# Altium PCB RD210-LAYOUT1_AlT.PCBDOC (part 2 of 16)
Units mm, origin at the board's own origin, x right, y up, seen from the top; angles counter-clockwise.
Board outline 330 x 300 mm, 6 copper layers (TOP, Mid-Layer 1, Mid-Layer 2, Mid-Layer 3, Mid-Layer 4, BOTTOM), stack 1.422 mm thick; 981 components, 463 nets, 2326 pads, 12534 vias.
Unrouted connection lines stored in the file: 6.
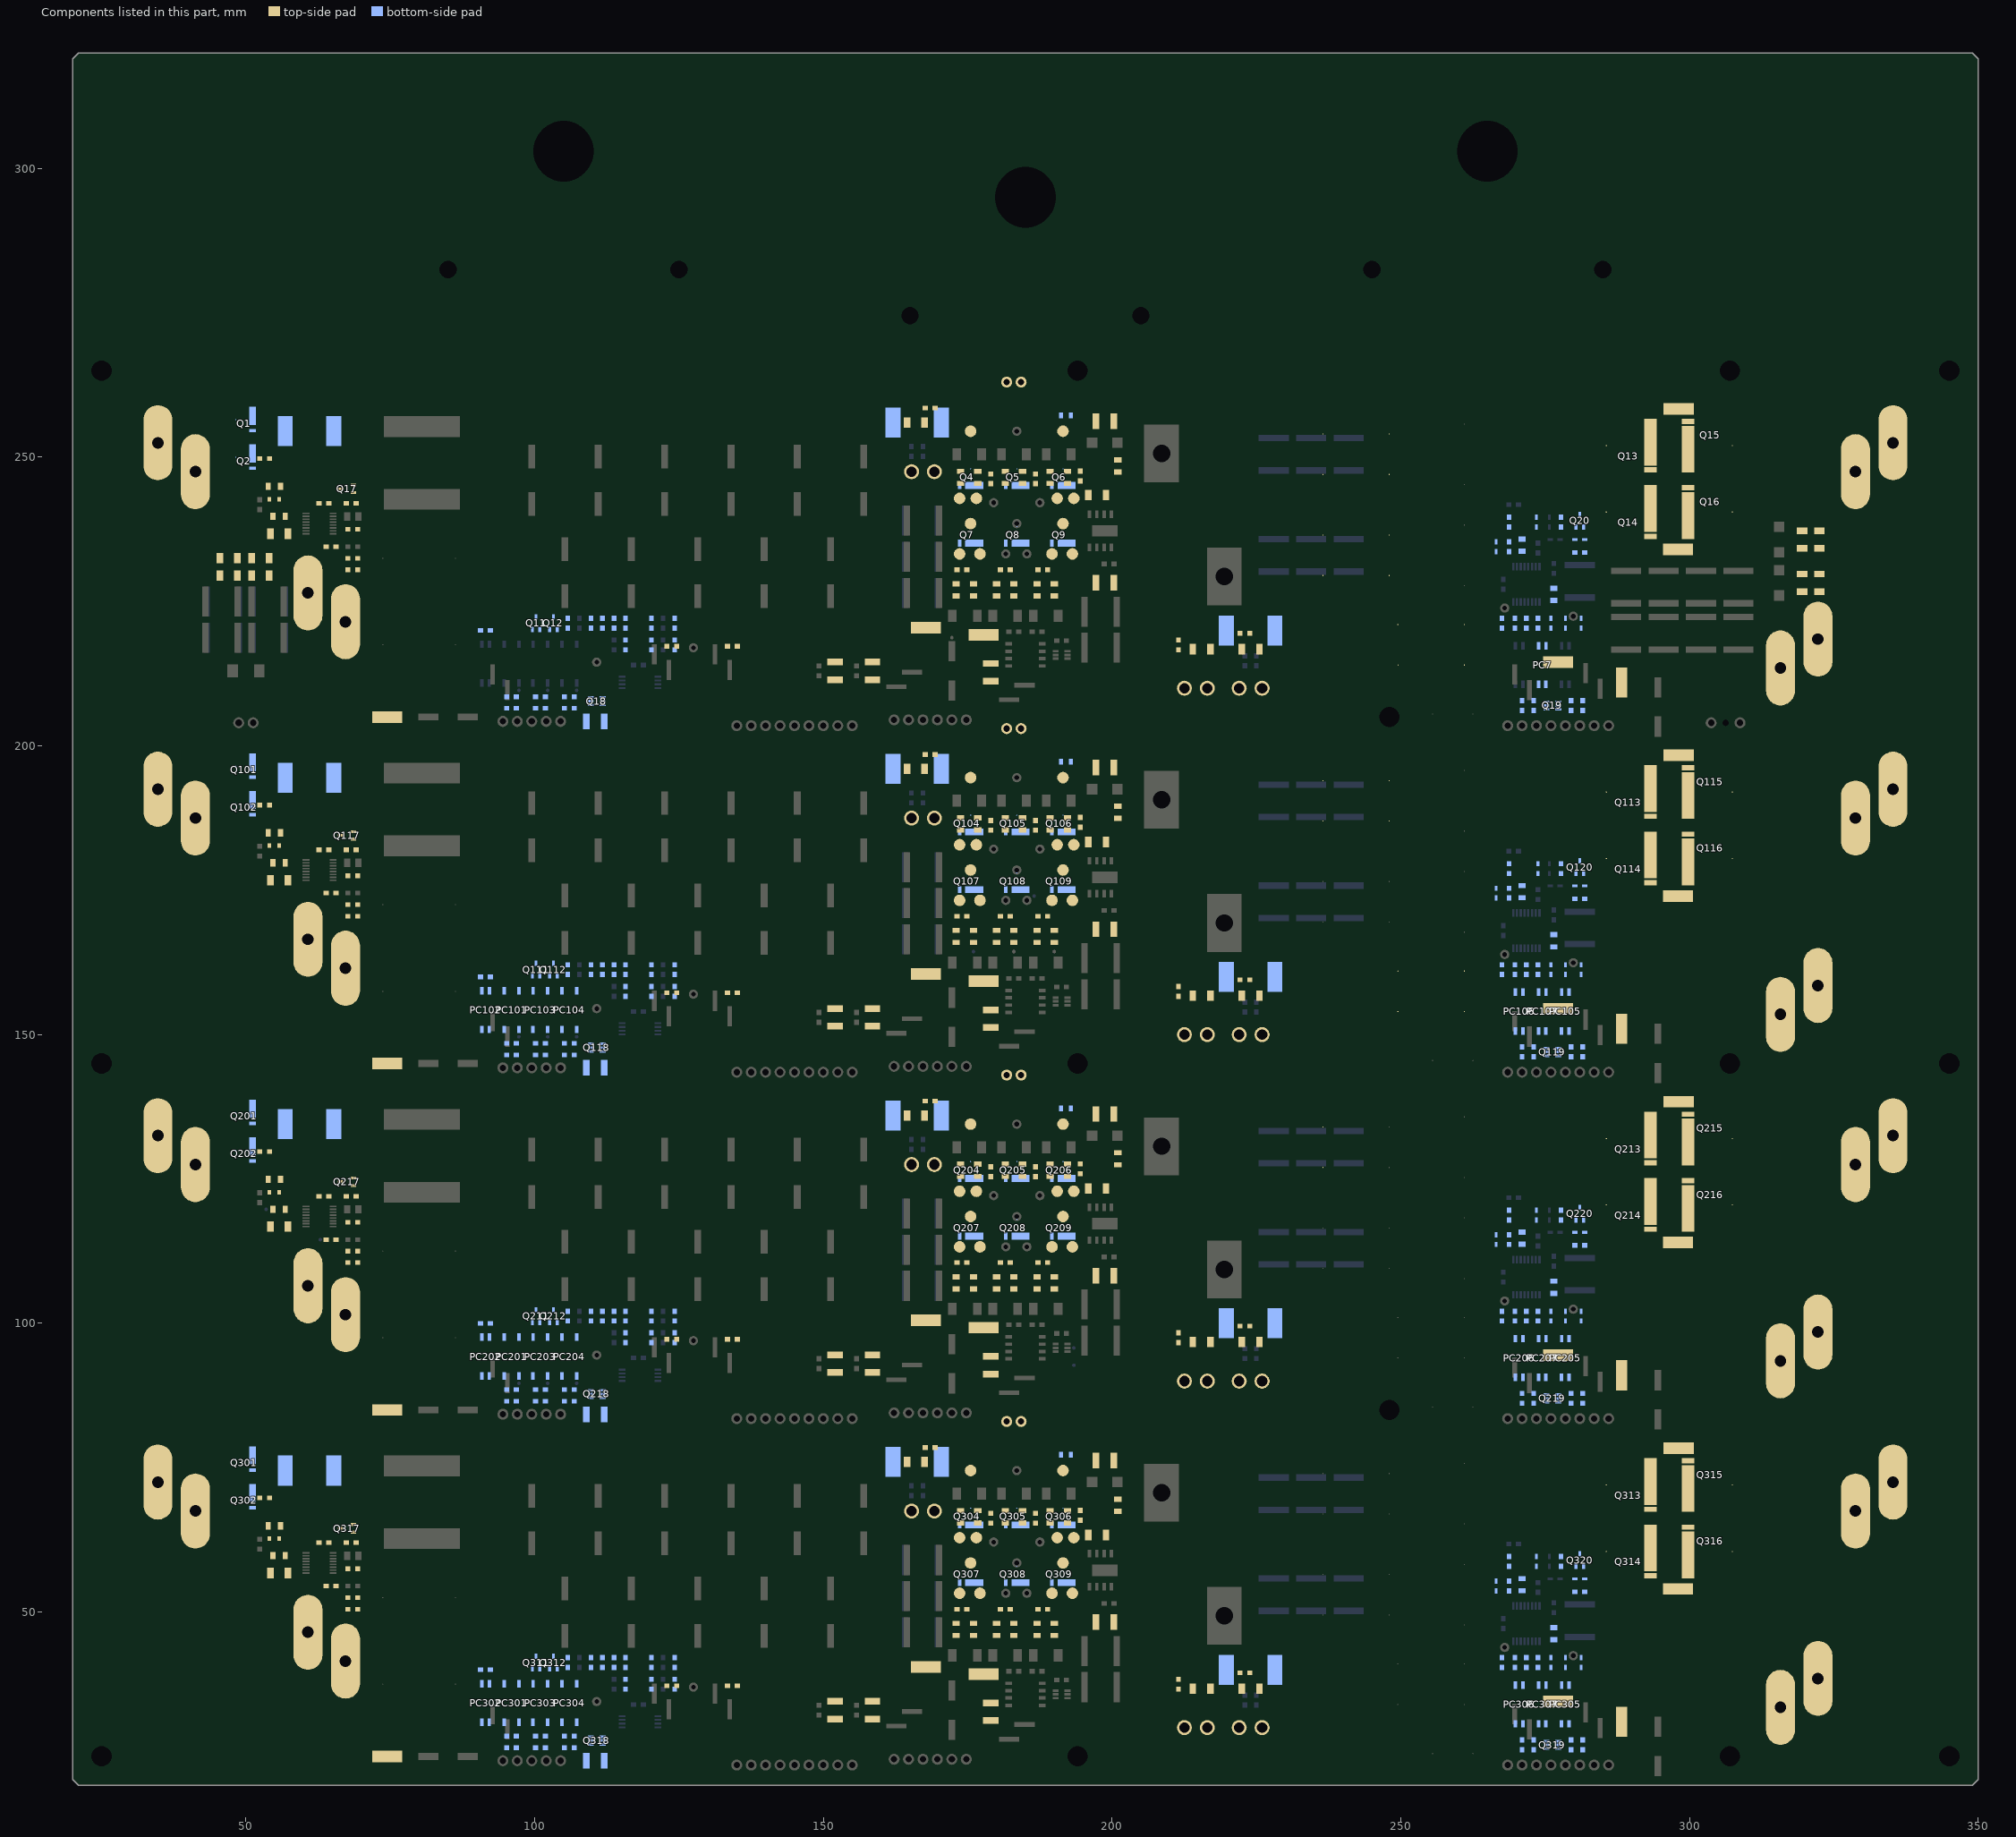
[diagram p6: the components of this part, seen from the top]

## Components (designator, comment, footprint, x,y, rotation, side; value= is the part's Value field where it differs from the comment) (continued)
PC7 "S4P_PC-2.6x4.55?2.1-PX1.27-PY7+3" S4P_PC-2.6x4.55?2.1-PX1.27-PY7+3 274.5,214 r180 bottom
PC101 "S4P_PC-3.7?4.55?2.1-PX2.54-PY7+3" S4P_PC-3.7?4.55?2.1-PX2.54-PY7+3 96,154.25 r0 bottom
PC102 "S4P_PC-2.6x4.55?2.1-PX1.27-PY7+4" S4P_PC-2.6x4.55?2.1-PX1.27-PY7+4 91.5,154.25 r180 bottom
PC103 "S4P_PC-3.7?4.55?2.1-PX2.54-PY7+4" S4P_PC-3.7?4.55?2.1-PX2.54-PY7+4 101,154.25 r0 bottom
PC104 "S4P_PC-3.7?4.55?2.1-PX2.54-PY7+5" S4P_PC-3.7?4.55?2.1-PX2.54-PY7+5 106,154.25 r0 bottom
PC105 "S4P_PC-2.6x4.55?2.1-PX1.27-PY7+5" S4P_PC-2.6x4.55?2.1-PX1.27-PY7+5 278.5,154 r0 bottom
PC106 "S4P_PC-2.6x4.55?2.1-PX1.27-PY7+6" S4P_PC-2.6x4.55?2.1-PX1.27-PY7+6 270.5,154 r0 bottom
PC107 "S4P_PC-2.6x4.55?2.1-PX1.27-PY7+7" S4P_PC-2.6x4.55?2.1-PX1.27-PY7+7 274.5,154 r180 bottom
PC201 "S4P_PC-3.7?4.55?2.1-PX2.54-PY7+6" S4P_PC-3.7?4.55?2.1-PX2.54-PY7+6 96,94.25 r0 bottom
PC202 "S4P_PC-2.6x4.55?2.1-PX1.27-PY7+8" S4P_PC-2.6x4.55?2.1-PX1.27-PY7+8 91.5,94.25 r180 bottom
PC203 "S4P_PC-3.7?4.55?2.1-PX2.54-PY7+7" S4P_PC-3.7?4.55?2.1-PX2.54-PY7+7 101,94.25 r0 bottom
PC204 "S4P_PC-3.7?4.55?2.1-PX2.54-PY7+8" S4P_PC-3.7?4.55?2.1-PX2.54-PY7+8 106,94.25 r0 bottom
PC205 "S4P_PC-2.6x4.55?2.1-PX1.27-PY7+9" S4P_PC-2.6x4.55?2.1-PX1.27-PY7+9 278.5,94 r0 bottom
PC206 "S4P_PC-2.6x4.55?2.1-PX1.27-PY7+10" S4P_PC-2.6x4.55?2.1-PX1.27-PY7+10 270.5,94 r0 bottom
PC207 "S4P_PC-2.6x4.55?2.1-PX1.27-PY7+11" S4P_PC-2.6x4.55?2.1-PX1.27-PY7+11 274.5,94 r180 bottom
PC301 "S4P_PC-3.7?4.55?2.1-PX2.54-PY7+9" S4P_PC-3.7?4.55?2.1-PX2.54-PY7+9 96,34.25 r0 bottom
PC302 "S4P_PC-2.6x4.55?2.1-PX1.27-PY7+12" S4P_PC-2.6x4.55?2.1-PX1.27-PY7+12 91.5,34.25 r180 bottom
PC303 "S4P_PC-3.7?4.55?2.1-PX2.54-PY7+10" S4P_PC-3.7?4.55?2.1-PX2.54-PY7+10 101,34.25 r0 bottom
PC304 "S4P_PC-3.7?4.55?2.1-PX2.54-PY7+11" S4P_PC-3.7?4.55?2.1-PX2.54-PY7+11 106,34.25 r0 bottom
PC305 "S4P_PC-2.6x4.55?2.1-PX1.27-PY7+13" S4P_PC-2.6x4.55?2.1-PX1.27-PY7+13 278.5,34 r0 bottom
PC306 "S4P_PC-2.6x4.55?2.1-PX1.27-PY7+14" S4P_PC-2.6x4.55?2.1-PX1.27-PY7+14 270.5,34 r0 bottom
PC307 "S4P_PC-2.6x4.55?2.1-PX1.27-PY7+15" S4P_PC-2.6x4.55?2.1-PX1.27-PY7+15 274.5,34 r180 bottom
Q1 "S3P_FET-5x5x1-PX1.27-PY6+22" S3P_FET-5x5x1-PX1.27-PY6+22 48.25,256.5 r90 bottom
Q2 "S3P_FET-5x5x1-PX1.27-PY6+23" S3P_FET-5x5x1-PX1.27-PY6+23 48.25,250 r90 bottom
Q4 "S3P_FET-5x5x1-PX1.27-PY6" S3P_FET-5x5x1-PX1.27-PY6 175.5,248 r0 bottom
Q5 "S3P_FET-5x5x1-PX1.27-PY6+2" S3P_FET-5x5x1-PX1.27-PY6+2 183.5,248 r0 bottom
Q6 "S3P_FET-5x5x1-PX1.27-PY6+4" S3P_FET-5x5x1-PX1.27-PY6+4 191.5,248 r0 bottom
Q7 "S3P_FET-5x5x1-PX1.27-PY6+1" S3P_FET-5x5x1-PX1.27-PY6+1 175.5,238 r0 bottom
Q8 "S3P_FET-5x5x1-PX1.27-PY6+3" S3P_FET-5x5x1-PX1.27-PY6+3 183.5,238 r0 bottom
Q9 "S3P_FET-5x5x1-PX1.27-PY6+5" S3P_FET-5x5x1-PX1.27-PY6+5 191.5,238 r0 bottom
Q11 "S3P_Q-2x1.7x0.75-PX0.65-2.1" S3P_Q-2x1.7x0.75-PX0.65-2.1 100.25,221.25 r0 bottom
Q12 "S3P_Q-2x1.7x0.75-PX0.65-2.1+1" S3P_Q-2x1.7x0.75-PX0.65-2.1+1 103.25,221.25 r0 bottom
Q13 "S3P_Q-9.9x8.5-2.3-PX1.2-PY11.8" S3P_Q-9.9x8.5-2.3-PX1.2-PY11.8 287,252 r90 top
Q14 "S3P_Q-9.9x8.5-2.3-PX1.2-PY11.8+1" S3P_Q-9.9x8.5-2.3-PX1.2-PY11.8+1 287,240.5 r90 top
Q15 "S3P_Q-9.9x8.5-2.3-PX1.2-PY11.8+2" S3P_Q-9.9x8.5-2.3-PX1.2-PY11.8+2 306,252 r270 top
Q16 "S3P_Q-9.9x8.5-2.3-PX1.2-PY11.8+3" S3P_Q-9.9x8.5-2.3-PX1.2-PY11.8+3 306,240.5 r270 top
Q17 "S3P_Q-2x1.7x0.75-PX0.65-2.1+8" S3P_Q-2x1.7x0.75-PX0.65-2.1+8 67.5,244.5 r90 top
Q18 "S6P_U-2x1.25x0.95-PX0.65-PY2.1" S6P_U-2x1.25x0.95-PX0.65-PY2.1 110.75,207.75 r270 bottom
Q19 "S6P_U-2x1.25x0.95-PX0.65-PY2.1+1" S6P_U-2x1.25x0.95-PX0.65-PY2.1+1 276.25,207 r90 bottom
Q20 "S3P_Q-2.0x1.25x0.9-PX0.65-PY2.1" S3P_Q-2.0x1.25x0.9-PX0.65-PY2.1 281,239 r0 bottom
Q101 "S3P_FET-5x5x1-PX1.27-PY6+24" S3P_FET-5x5x1-PX1.27-PY6+24 48.25,196.5 r90 bottom
Q102 "S3P_FET-5x5x1-PX1.27-PY6+25" S3P_FET-5x5x1-PX1.27-PY6+25 48.25,190 r90 bottom
Q104 "S3P_FET-5x5x1-PX1.27-PY6+26" S3P_FET-5x5x1-PX1.27-PY6+26 175.5,188 r0 bottom
Q105 "S3P_FET-5x5x1-PX1.27-PY6+27" S3P_FET-5x5x1-PX1.27-PY6+27 183.5,188 r0 bottom
Q106 "S3P_FET-5x5x1-PX1.27-PY6+28" S3P_FET-5x5x1-PX1.27-PY6+28 191.5,188 r0 bottom
Q107 "S3P_FET-5x5x1-PX1.27-PY6+29" S3P_FET-5x5x1-PX1.27-PY6+29 175.5,178 r0 bottom
Q108 "S3P_FET-5x5x1-PX1.27-PY6+30" S3P_FET-5x5x1-PX1.27-PY6+30 183.5,178 r0 bottom
Q109 "S3P_FET-5x5x1-PX1.27-PY6+31" S3P_FET-5x5x1-PX1.27-PY6+31 191.5,178 r0 bottom
Q111 "S3P_Q-2x1.7x0.75-PX0.65-2.1+2" S3P_Q-2x1.7x0.75-PX0.65-2.1+2 100.25,161.25 r0 bottom
Q112 "S3P_Q-2x1.7x0.75-PX0.65-2.1+3" S3P_Q-2x1.7x0.75-PX0.65-2.1+3 103.25,161.25 r0 bottom
Q113 "S3P_Q-9.9x8.5-2.3-PX1.2-PY11.8+5" S3P_Q-9.9x8.5-2.3-PX1.2-PY11.8+5 287,192 r90 top
Q114 "S3P_Q-9.9x8.5-2.3-PX1.2-PY11.8+4" S3P_Q-9.9x8.5-2.3-PX1.2-PY11.8+4 287,180.5 r90 top
Q115 "S3P_Q-9.9x8.5-2.3-PX1.2-PY11.8+7" S3P_Q-9.9x8.5-2.3-PX1.2-PY11.8+7 306,192 r270 top
Q116 "S3P_Q-9.9x8.5-2.3-PX1.2-PY11.8+6" S3P_Q-9.9x8.5-2.3-PX1.2-PY11.8+6 306,180.5 r270 top
Q117 "S3P_Q-2x1.7x0.75-PX0.65-2.1+9" S3P_Q-2x1.7x0.75-PX0.65-2.1+9 67.5,184.5 r90 top
Q118 "S6P_U-2x1.25x0.95-PX0.65-PY2.1+2" S6P_U-2x1.25x0.95-PX0.65-PY2.1+2 110.75,147.75 r270 bottom
Q119 "S6P_U-2x1.25x0.95-PX0.65-PY2.1+3" S6P_U-2x1.25x0.95-PX0.65-PY2.1+3 276.25,147 r90 bottom
Q120 "S3P_Q-2.0x1.25x0.9-PX0.65-PY2.1+1" S3P_Q-2.0x1.25x0.9-PX0.65-PY2.1+1 281,179 r0 bottom
Q201 "S3P_FET-5x5x1-PX1.27-PY6+6" S3P_FET-5x5x1-PX1.27-PY6+6 48.25,136.5 r90 bottom
Q202 "S3P_FET-5x5x1-PX1.27-PY6+7" S3P_FET-5x5x1-PX1.27-PY6+7 48.25,130 r90 bottom
Q204 "S3P_FET-5x5x1-PX1.27-PY6+8" S3P_FET-5x5x1-PX1.27-PY6+8 175.5,128 r0 bottom
Q205 "S3P_FET-5x5x1-PX1.27-PY6+9" S3P_FET-5x5x1-PX1.27-PY6+9 183.5,128 r0 bottom
Q206 "S3P_FET-5x5x1-PX1.27-PY6+10" S3P_FET-5x5x1-PX1.27-PY6+10 191.5,128 r0 bottom
Q207 "S3P_FET-5x5x1-PX1.27-PY6+11" S3P_FET-5x5x1-PX1.27-PY6+11 175.5,118 r0 bottom
Q208 "S3P_FET-5x5x1-PX1.27-PY6+12" S3P_FET-5x5x1-PX1.27-PY6+12 183.5,118 r0 bottom
Q209 "S3P_FET-5x5x1-PX1.27-PY6+13" S3P_FET-5x5x1-PX1.27-PY6+13 191.5,118 r0 bottom
Q211 "S3P_Q-2x1.7x0.75-PX0.65-2.1+4" S3P_Q-2x1.7x0.75-PX0.65-2.1+4 100.25,101.25 r0 bottom
Q212 "S3P_Q-2x1.7x0.75-PX0.65-2.1+5" S3P_Q-2x1.7x0.75-PX0.65-2.1+5 103.25,101.25 r0 bottom
Q213 "S3P_Q-9.9x8.5-2.3-PX1.2-PY11.8+9" S3P_Q-9.9x8.5-2.3-PX1.2-PY11.8+9 287,132 r90 top
Q214 "S3P_Q-9.9x8.5-2.3-PX1.2-PY11.8+8" S3P_Q-9.9x8.5-2.3-PX1.2-PY11.8+8 287,120.5 r90 top
Q215 "S3P_Q-9.9x8.5-2.3-PX1.2-PY11.8+11" S3P_Q-9.9x8.5-2.3-PX1.2-PY11.8+11 306,132 r270 top
Q216 "S3P_Q-9.9x8.5-2.3-PX1.2-PY11.8+10" S3P_Q-9.9x8.5-2.3-PX1.2-PY11.8+10 306,120.5 r270 top
Q217 "S3P_Q-2x1.7x0.75-PX0.65-2.1+10" S3P_Q-2x1.7x0.75-PX0.65-2.1+10 67.5,124.5 r90 top
Q218 "S6P_U-2x1.25x0.95-PX0.65-PY2.1+4" S6P_U-2x1.25x0.95-PX0.65-PY2.1+4 110.75,87.75 r270 bottom
Q219 "S6P_U-2x1.25x0.95-PX0.65-PY2.1+5" S6P_U-2x1.25x0.95-PX0.65-PY2.1+5 276.25,87 r90 bottom
Q220 "S3P_Q-2.0x1.25x0.9-PX0.65-PY2.1+2" S3P_Q-2.0x1.25x0.9-PX0.65-PY2.1+2 281,119 r0 bottom
Q301 "S3P_FET-5x5x1-PX1.27-PY6+14" S3P_FET-5x5x1-PX1.27-PY6+14 48.25,76.5 r90 bottom
Q302 "S3P_FET-5x5x1-PX1.27-PY6+15" S3P_FET-5x5x1-PX1.27-PY6+15 48.25,70 r90 bottom
Q304 "S3P_FET-5x5x1-PX1.27-PY6+16" S3P_FET-5x5x1-PX1.27-PY6+16 175.5,68 r0 bottom
Q305 "S3P_FET-5x5x1-PX1.27-PY6+17" S3P_FET-5x5x1-PX1.27-PY6+17 183.5,68 r0 bottom
Q306 "S3P_FET-5x5x1-PX1.27-PY6+18" S3P_FET-5x5x1-PX1.27-PY6+18 191.5,68 r0 bottom
Q307 "S3P_FET-5x5x1-PX1.27-PY6+19" S3P_FET-5x5x1-PX1.27-PY6+19 175.5,58 r0 bottom
Q308 "S3P_FET-5x5x1-PX1.27-PY6+20" S3P_FET-5x5x1-PX1.27-PY6+20 183.5,58 r0 bottom
Q309 "S3P_FET-5x5x1-PX1.27-PY6+21" S3P_FET-5x5x1-PX1.27-PY6+21 191.5,58 r0 bottom
Q311 "S3P_Q-2x1.7x0.75-PX0.65-2.1+6" S3P_Q-2x1.7x0.75-PX0.65-2.1+6 100.25,41.25 r0 bottom
Q312 "S3P_Q-2x1.7x0.75-PX0.65-2.1+7" S3P_Q-2x1.7x0.75-PX0.65-2.1+7 103.25,41.25 r0 bottom
Q313 "S3P_Q-9.9x8.5-2.3-PX1.2-PY11.8+13" S3P_Q-9.9x8.5-2.3-PX1.2-PY11.8+13 287,72 r90 top
Q314 "S3P_Q-9.9x8.5-2.3-PX1.2-PY11.8+12" S3P_Q-9.9x8.5-2.3-PX1.2-PY11.8+12 287,60.5 r90 top
Q315 "S3P_Q-9.9x8.5-2.3-PX1.2-PY11.8+15" S3P_Q-9.9x8.5-2.3-PX1.2-PY11.8+15 306,72 r270 top
Q316 "S3P_Q-9.9x8.5-2.3-PX1.2-PY11.8+14" S3P_Q-9.9x8.5-2.3-PX1.2-PY11.8+14 306,60.5 r270 top
Q317 "S3P_Q-2x1.7x0.75-PX0.65-2.1+11" S3P_Q-2x1.7x0.75-PX0.65-2.1+11 67.5,64.5 r90 top
Q318 "S6P_U-2x1.25x0.95-PX0.65-PY2.1+6" S6P_U-2x1.25x0.95-PX0.65-PY2.1+6 110.75,27.75 r270 bottom
Q319 "S6P_U-2x1.25x0.95-PX0.65-PY2.1+7" S6P_U-2x1.25x0.95-PX0.65-PY2.1+7 276.25,27 r90 bottom
Q320 "S3P_Q-2.0x1.25x0.9-PX0.65-PY2.1+3" S3P_Q-2.0x1.25x0.9-PX0.65-PY2.1+3 281,59 r0 bottom
R1 "S2P_R-2x1.25x0.5-PX2" S2P_R-2x1.25x0.5-PX2 55.75,239.75 r180 top
R2 "_RK73G1JTTD1003D_" _RK73G1JTTD1003D_ 64.75,234.5 r180 top
R3 "S2P_R-1.6x0.8x0.45-PX1.6+56" S2P_R-1.6x0.8x0.45-PX1.6+56 68.5,232.5 r180 top
R4 "_RK73G1JTTD1801D_" _RK73G1JTTD1801D_ 68.5,230.5 r0 top
R7 "_RK73H1JTTD1004F_" _RK73H1JTTD1004F_ 53.25,249.75 r0 top
R8 "S2P_R-10x5.2x1.3-PX10+9" S2P_R-10x5.2x1.3-PX10+9 61,254.5 r180 bottom
R9 "S2P_R-2x1.25x0.5-PX2+4" S2P_R-2x1.25x0.5-PX2+4 201,248.5 r90 top
R10 "_SG73P2ATTD1R0J_" _SG73P2ATTD1R0J_ 173.75,246.5 r270 top
R11 "_SG73P2ATTD100J_" _SG73P2ATTD100J_ 176.75,246.5 r270 top
R12 "_RK73B1JTTD103J_" _RK73B1JTTD103J_ 179,246.25 r90 top
R13 "_SG73P2ATTD1R0J_+19" _SG73P2ATTD1R0J_+19 181.5,246.5 r270 top
R14 "_SG73P2ATTD100J_+19" _SG73P2ATTD100J_+19 184.5,246.5 r270 top
R15 "_RK73B1JTTD103J_+2" _RK73B1JTTD103J_+2 186.75,246.25 r90 top
R16 "_SG73P2ATTD1R0J_+20" _SG73P2ATTD1R0J_+20 189.25,246.5 r270 top
R17 "_SG73P2ATTD100J_+20" _SG73P2ATTD100J_+20 192.25,246.5 r270 top
R18 "_RK73B1JTTD103J_+4" _RK73B1JTTD103J_+4 194.5,246.75 r90 top
R20 "_SG73P2ATTD1R0J_+21" _SG73P2ATTD1R0J_+21 173,227 r90 top
R21 "_SG73P2ATTD100J_+21" _SG73P2ATTD100J_+21 176,227 r90 top
R22 "_RK73B1JTTD103J_+1" _RK73B1JTTD103J_+1 174,230.5 r0 top
R23 "_SG73P2ATTD1R0J_+22" _SG73P2ATTD1R0J_+22 180,227 r90 top
R24 "_SG73P2ATTD100J_+22" _SG73P2ATTD100J_+22 183,227 r90 top
R25 "_RK73B1JTTD103J_+3" _RK73B1JTTD103J_+3 181.5,230.5 r0 top
R26 "_SG73P2ATTD1R0J_+23" _SG73P2ATTD1R0J_+23 187,227 r90 top
R27 "_SG73P2ATTD100J_+23" _SG73P2ATTD100J_+23 190,227 r90 top
R28 "_RK73B1JTTD103J_+5" _RK73B1JTTD103J_+5 188,230.5 r0 top
R29 "S2P_R-10x5.2x1.3-PX10" S2P_R-10x5.2x1.3-PX10 166.25,256 r180 bottom
R38 "S2P_R-10x5.2x1.3-PX10+11" S2P_R-10x5.2x1.3-PX10+11 224,220 r180 bottom
R47 "_RK73G1JTTD10R0D_" _RK73G1JTTD10R0D_ 123.75,217.25 r180 top
R48 "_RK73G1JTTD2002D_+4" _RK73G1JTTD2002D_+4 115.75,221.25 r270 bottom
R49 "_RK73G1JTTD2002D_" _RK73G1JTTD2002D_ 113.75,221.25 r90 bottom
R50 "_RK73G1JTTD1001D_+15" _RK73G1JTTD1001D_+15 124.25,221.25 r270 bottom
R51 "_RK73G1JTTD2002D_+15" _RK73G1JTTD2002D_+15 120.25,221.25 r90 bottom
R52 "_RK73G1JTTD2002D_+14" _RK73G1JTTD2002D_+14 120.25,217.5 r90 bottom
R53 "_RK73G1JTTD1001D_+1" _RK73G1JTTD1001D_+1 124.25,217.5 r270 bottom
R55 "_RK73G1JTTD10R0D_+7" _RK73G1JTTD10R0D_+7 134.25,217.25 r0 top
R56 "_RK73G1JTTD1102D_" _RK73G1JTTD1102D_ 105.75,221.25 r270 bottom
R57 "_RK73G1JTTD1001D_+2" _RK73G1JTTD1001D_+2 109.75,221.25 r270 bottom
R58 "_RK73G1JTTD1102D_+1" _RK73G1JTTD1102D_+1 111.75,221.25 r90 bottom
R59 "_RK73G1JTTD1001D_" _RK73G1JTTD1001D_ 115.75,217.5 r90 bottom
R60 "_SG73P2ATTD2R2J_" _SG73P2ATTD2R2J_ 276.5,226.25 r270 bottom
R63 "_RK73H1JTTD3303F_" _RK73H1JTTD3303F_ 277.75,238.75 r270 bottom
R64 "S2P_R-1.6x0.8x0.45-PX1.6" S2P_R-1.6x0.8x0.45-PX1.6 63.5,242 r180 top
R65 "S2P_R-1.6x0.8x0.45-PX1.6+1" S2P_R-1.6x0.8x0.45-PX1.6+1 68.25,242 r180 top
R66 "S2P_R-1.6x0.8x0.45-PX1.6+12" S2P_R-1.6x0.8x0.45-PX1.6+12 96,208.5 r180 bottom
R67 "S2P_R-1.6x0.8x0.45-PX1.6+40" S2P_R-1.6x0.8x0.45-PX1.6+40 96,206.5 r180 bottom
R68 "S2P_R-1.6x0.8x0.45-PX1.6+13" S2P_R-1.6x0.8x0.45-PX1.6+13 101,208.5 r180 bottom
R69 "S2P_R-1.6x0.8x0.45-PX1.6+41" S2P_R-1.6x0.8x0.45-PX1.6+41 101,206.5 r0 bottom
R70 "S2P_R-1.6x0.8x0.45-PX1.6+8" S2P_R-1.6x0.8x0.45-PX1.6+8 68.5,237.5 r0 top
R71 "S2P_R-1.6x0.8x0.45-PX1.6+14" S2P_R-1.6x0.8x0.45-PX1.6+14 91.5,220 r0 bottom
R72 "S2P_R-1.6x0.8x0.45-PX1.6+42" S2P_R-1.6x0.8x0.45-PX1.6+42 106,206.5 r0 bottom
R73 "S2P_R-1.6x0.8x0.45-PX1.6+15" S2P_R-1.6x0.8x0.45-PX1.6+15 106,208.5 r180 bottom
R81 "_SG73P1JTTD473J_" _SG73P1JTTD473J_ 268.75,234.5 r270 bottom
R82 "_SG73P2ATTD912J_+1" _SG73P2ATTD912J_+1 271,234.75 r270 bottom
R84 "_RK73B1JTTD222J_" _RK73B1JTTD222J_ 279.5,207 r270 bottom
R85 "_RK73B1JTTD222J_+1" _RK73B1JTTD222J_+1 273,207 r90 bottom
R86 "S2P_R-1.6x0.8x0.45-PX1.6+16" S2P_R-1.6x0.8x0.45-PX1.6+16 281.5,207 r270 bottom
R87 "S2P_R-1.6x0.8x0.45-PX1.6+17" S2P_R-1.6x0.8x0.45-PX1.6+17 271,207 r270 bottom
R88 "_RK73B1JTTD473J_" _RK73B1JTTD473J_ 267.5,221.25 r90 bottom
R89 "_RK73B1JTTD473J_+1" _RK73B1JTTD473J_+1 273.75,221.25 r90 bottom
R90 "S2P_R-1.6x0.8x0.45-PX1.6+52" S2P_R-1.6x0.8x0.45-PX1.6+52 271.75,221.25 r90 bottom
R91 "S2P_R-1.6x0.8x0.45-PX1.6+18" S2P_R-1.6x0.8x0.45-PX1.6+18 269.75,221.25 r270 bottom
R92 "_SG73P1JTTD473J_+1" _SG73P1JTTD473J_+1 268.75,238.75 r270 bottom
R93 "_RK73B1JTTD334J_" _RK73B1JTTD334J_ 281,233.5 r180 bottom
R101 "S2P_R-2x1.25x0.5-PX2+1" S2P_R-2x1.25x0.5-PX2+1 55.75,179.75 r180 top
R102 "_RK73G1JTTD1003D_+1" _RK73G1JTTD1003D_+1 64.75,174.5 r180 top
R103 "S2P_R-1.6x0.8x0.45-PX1.6+57" S2P_R-1.6x0.8x0.45-PX1.6+57 68.5,172.5 r180 top
R104 "_RK73G1JTTD1801D_+1" _RK73G1JTTD1801D_+1 68.5,170.5 r0 top
R107 "_RK73H1JTTD1004F_+1" _RK73H1JTTD1004F_+1 53.25,189.75 r0 top
R108 "S2P_R-10x5.2x1.3-PX10+10" S2P_R-10x5.2x1.3-PX10+10 61,194.5 r180 bottom
R109 "S2P_R-2x1.25x0.5-PX2+5" S2P_R-2x1.25x0.5-PX2+5 201,188.5 r90 top
R110 "_SG73P2ATTD1R0J_+1" _SG73P2ATTD1R0J_+1 173.75,186.5 r270 top
R111 "_SG73P2ATTD100J_+1" _SG73P2ATTD100J_+1 176.75,186.5 r270 top
R112 "_RK73B1JTTD103J_+6" _RK73B1JTTD103J_+6 179,186.25 r90 top
R113 "_SG73P2ATTD1R0J_+2" _SG73P2ATTD1R0J_+2 181.5,186.5 r270 top
R114 "_SG73P2ATTD100J_+2" _SG73P2ATTD100J_+2 184.5,186.5 r270 top
R115 "_RK73B1JTTD103J_+7" _RK73B1JTTD103J_+7 186.75,186.25 r90 top
R116 "_SG73P2ATTD1R0J_+3" _SG73P2ATTD1R0J_+3 189.25,186.5 r270 top
R117 "_SG73P2ATTD100J_+3" _SG73P2ATTD100J_+3 192.25,186.5 r270 top
R118 "_RK73B1JTTD103J_+8" _RK73B1JTTD103J_+8 194.5,186.75 r90 top
R120 "_SG73P2ATTD1R0J_+4" _SG73P2ATTD1R0J_+4 173,167 r90 top
R121 "_SG73P2ATTD100J_+4" _SG73P2ATTD100J_+4 176,167 r90 top
R122 "_RK73B1JTTD103J_+9" _RK73B1JTTD103J_+9 174,170.5 r0 top
R123 "_SG73P2ATTD1R0J_+5" _SG73P2ATTD1R0J_+5 180,167 r90 top
R124 "_SG73P2ATTD100J_+5" _SG73P2ATTD100J_+5 183,167 r90 top
R125 "_RK73B1JTTD103J_+10" _RK73B1JTTD103J_+10 181.5,170.5 r0 top
R126 "_SG73P2ATTD1R0J_+6" _SG73P2ATTD1R0J_+6 187,167 r90 top
R127 "_SG73P2ATTD100J_+6" _SG73P2ATTD100J_+6 190,167 r90 top
R128 "_RK73B1JTTD103J_+11" _RK73B1JTTD103J_+11 188,170.5 r0 top
R129 "S2P_R-10x5.2x1.3-PX10+1" S2P_R-10x5.2x1.3-PX10+1 166.25,196 r180 bottom
R138 "S2P_R-10x5.2x1.3-PX10+2" S2P_R-10x5.2x1.3-PX10+2 224,160 r180 bottom
R147 "_RK73G1JTTD10R0D_+1" _RK73G1JTTD10R0D_+1 123.75,157.25 r180 top
R148 "_RK73G1JTTD2002D_+5" _RK73G1JTTD2002D_+5 115.75,161.25 r270 bottom
R149 "_RK73G1JTTD2002D_+6" _RK73G1JTTD2002D_+6 113.75,161.25 r90 bottom
R150 "_RK73G1JTTD1001D_+3" _RK73G1JTTD1001D_+3 124.25,161.25 r270 bottom
R151 "_RK73G1JTTD2002D_+7" _RK73G1JTTD2002D_+7 120.25,161.25 r90 bottom
R152 "_RK73G1JTTD2002D_+1" _RK73G1JTTD2002D_+1 120.25,157.5 r90 bottom
R153 "_RK73G1JTTD1001D_+4" _RK73G1JTTD1001D_+4 124.25,157.5 r270 bottom
R155 "_RK73G1JTTD10R0D_+2" _RK73G1JTTD10R0D_+2 134.25,157.25 r0 top
R156 "_RK73G1JTTD1102D_+2" _RK73G1JTTD1102D_+2 105.75,161.25 r270 bottom
R157 "_RK73G1JTTD1001D_+5" _RK73G1JTTD1001D_+5 109.75,161.25 r270 bottom
R158 "_RK73G1JTTD1102D_+3" _RK73G1JTTD1102D_+3 111.75,161.25 r90 bottom
R159 "_RK73G1JTTD1001D_+6" _RK73G1JTTD1001D_+6 115.75,157.5 r90 bottom
R160 "_SG73P2ATTD2R2J_+1" _SG73P2ATTD2R2J_+1 276.5,166.25 r270 bottom
R163 "_RK73H1JTTD3303F_+1" _RK73H1JTTD3303F_+1 277.75,178.75 r270 bottom
R164 "S2P_R-1.6x0.8x0.45-PX1.6+2" S2P_R-1.6x0.8x0.45-PX1.6+2 63.5,182 r180 top
R165 "S2P_R-1.6x0.8x0.45-PX1.6+3" S2P_R-1.6x0.8x0.45-PX1.6+3 68.25,182 r180 top
R166 "S2P_R-1.6x0.8x0.45-PX1.6+19" S2P_R-1.6x0.8x0.45-PX1.6+19 96,148.5 r180 bottom
R167 "S2P_R-1.6x0.8x0.45-PX1.6+43" S2P_R-1.6x0.8x0.45-PX1.6+43 96,146.5 r180 bottom
R168 "S2P_R-1.6x0.8x0.45-PX1.6+20" S2P_R-1.6x0.8x0.45-PX1.6+20 101,148.5 r180 bottom
R169 "S2P_R-1.6x0.8x0.45-PX1.6+44" S2P_R-1.6x0.8x0.45-PX1.6+44 101,146.5 r0 bottom
R170 "S2P_R-1.6x0.8x0.45-PX1.6+9" S2P_R-1.6x0.8x0.45-PX1.6+9 68.5,177.5 r0 top
R171 "S2P_R-1.6x0.8x0.45-PX1.6+21" S2P_R-1.6x0.8x0.45-PX1.6+21 91.5,160 r0 bottom
R172 "S2P_R-1.6x0.8x0.45-PX1.6+45" S2P_R-1.6x0.8x0.45-PX1.6+45 106,146.5 r0 bottom
R173 "S2P_R-1.6x0.8x0.45-PX1.6+22" S2P_R-1.6x0.8x0.45-PX1.6+22 106,148.5 r180 bottom
R181 "_SG73P1JTTD473J_+2" _SG73P1JTTD473J_+2 268.75,174.5 r270 bottom
R182 "_SG73P2ATTD912J_+2" _SG73P2ATTD912J_+2 271,174.75 r270 bottom
R184 "_RK73B1JTTD222J_+2" _RK73B1JTTD222J_+2 279.5,147 r270 bottom
R185 "_RK73B1JTTD222J_+3" _RK73B1JTTD222J_+3 273,147 r90 bottom
R186 "S2P_R-1.6x0.8x0.45-PX1.6+23" S2P_R-1.6x0.8x0.45-PX1.6+23 281.5,147 r270 bottom
R187 "S2P_R-1.6x0.8x0.45-PX1.6+24" S2P_R-1.6x0.8x0.45-PX1.6+24 271,147 r270 bottom
R188 "_RK73B1JTTD473J_+2" _RK73B1JTTD473J_+2 267.5,161.25 r90 bottom
R189 "_RK73B1JTTD473J_+3" _RK73B1JTTD473J_+3 273.75,161.25 r90 bottom
R190 "S2P_R-1.6x0.8x0.45-PX1.6+53" S2P_R-1.6x0.8x0.45-PX1.6+53 271.75,161.25 r90 bottom
R191 "S2P_R-1.6x0.8x0.45-PX1.6+25" S2P_R-1.6x0.8x0.45-PX1.6+25 269.75,161.25 r270 bottom
R192 "_SG73P1JTTD473J_+3" _SG73P1JTTD473J_+3 268.75,178.75 r270 bottom
R193 "_RK73B1JTTD334J_+1" _RK73B1JTTD334J_+1 281,173.5 r180 bottom
R201 "S2P_R-2x1.25x0.5-PX2+2" S2P_R-2x1.25x0.5-PX2+2 55.75,119.75 r180 top
R202 "_RK73G1JTTD1003D_+2" _RK73G1JTTD1003D_+2 64.75,114.5 r180 top
R203 "S2P_R-1.6x0.8x0.45-PX1.6+58" S2P_R-1.6x0.8x0.45-PX1.6+58 68.5,112.5 r180 top
R204 "_RK73G1JTTD1801D_+2" _RK73G1JTTD1801D_+2 68.5,110.5 r0 top
R207 "_RK73H1JTTD1004F_+2" _RK73H1JTTD1004F_+2 53.25,129.75 r0 top
R208 "S2P_R-10x5.2x1.3-PX10+3" S2P_R-10x5.2x1.3-PX10+3 61,134.5 r180 bottom
R209 "S2P_R-2x1.25x0.5-PX2+6" S2P_R-2x1.25x0.5-PX2+6 201,128.5 r90 top
R210 "_SG73P2ATTD1R0J_+7" _SG73P2ATTD1R0J_+7 173.75,126.5 r270 top
R211 "_SG73P2ATTD100J_+7" _SG73P2ATTD100J_+7 176.75,126.5 r270 top
R212 "_RK73B1JTTD103J_+12" _RK73B1JTTD103J_+12 179,126.25 r90 top
R213 "_SG73P2ATTD1R0J_+8" _SG73P2ATTD1R0J_+8 181.5,126.5 r270 top
R214 "_SG73P2ATTD100J_+8" _SG73P2ATTD100J_+8 184.5,126.5 r270 top
R215 "_RK73B1JTTD103J_+13" _RK73B1JTTD103J_+13 186.75,126.25 r90 top
R216 "_SG73P2ATTD1R0J_+9" _SG73P2ATTD1R0J_+9 189.25,126.5 r270 top
R217 "_SG73P2ATTD100J_+9" _SG73P2ATTD100J_+9 192.25,126.5 r270 top
R218 "_RK73B1JTTD103J_+14" _RK73B1JTTD103J_+14 194.5,126.75 r90 top
R220 "_SG73P2ATTD1R0J_+10" _SG73P2ATTD1R0J_+10 173,107 r90 top
R221 "_SG73P2ATTD100J_+10" _SG73P2ATTD100J_+10 176,107 r90 top
R222 "_RK73B1JTTD103J_+15" _RK73B1JTTD103J_+15 174,110.5 r0 top
R223 "_SG73P2ATTD1R0J_+11" _SG73P2ATTD1R0J_+11 180,107 r90 top
R224 "_SG73P2ATTD100J_+11" _SG73P2ATTD100J_+11 183,107 r90 top
R225 "_RK73B1JTTD103J_+16" _RK73B1JTTD103J_+16 181.5,110.5 r0 top
R226 "_SG73P2ATTD1R0J_+12" _SG73P2ATTD1R0J_+12 187,107 r90 top
R227 "_SG73P2ATTD100J_+12" _SG73P2ATTD100J_+12 190,107 r90 top
R228 "_RK73B1JTTD103J_+17" _RK73B1JTTD103J_+17 188,110.5 r0 top
R229 "S2P_R-10x5.2x1.3-PX10+4" S2P_R-10x5.2x1.3-PX10+4 166.25,136 r180 bottom
R238 "S2P_R-10x5.2x1.3-PX10+5" S2P_R-10x5.2x1.3-PX10+5 224,100 r180 bottom
R247 "_RK73G1JTTD10R0D_+3" _RK73G1JTTD10R0D_+3 123.75,97.25 r180 top
R248 "_RK73G1JTTD2002D_+8" _RK73G1JTTD2002D_+8 115.75,101.25 r270 bottom
R249 "_RK73G1JTTD2002D_+9" _RK73G1JTTD2002D_+9 113.75,101.25 r90 bottom
R250 "_RK73G1JTTD1001D_+7" _RK73G1JTTD1001D_+7 124.25,101.25 r270 bottom
R251 "_RK73G1JTTD2002D_+10" _RK73G1JTTD2002D_+10 120.25,101.25 r90 bottom
R252 "_RK73G1JTTD2002D_+2" _RK73G1JTTD2002D_+2 120.25,97.5 r90 bottom
R253 "_RK73G1JTTD1001D_+8" _RK73G1JTTD1001D_+8 124.25,97.5 r270 bottom
R255 "_RK73G1JTTD10R0D_+4" _RK73G1JTTD10R0D_+4 134.25,97.25 r0 top
R256 "_RK73G1JTTD1102D_+4" _RK73G1JTTD1102D_+4 105.75,101.25 r270 bottom
R257 "_RK73G1JTTD1001D_+9" _RK73G1JTTD1001D_+9 109.75,101.25 r270 bottom
R258 "_RK73G1JTTD1102D_+5" _RK73G1JTTD1102D_+5 111.75,101.25 r90 bottom
R259 "_RK73G1JTTD1001D_+10" _RK73G1JTTD1001D_+10 115.75,97.5 r90 bottom
R260 "_SG73P2ATTD2R2J_+2" _SG73P2ATTD2R2J_+2 276.5,106.25 r270 bottom
R263 "_RK73H1JTTD3303F_+2" _RK73H1JTTD3303F_+2 277.75,118.75 r270 bottom
R264 "S2P_R-1.6x0.8x0.45-PX1.6+4" S2P_R-1.6x0.8x0.45-PX1.6+4 63.5,122 r180 top
R265 "S2P_R-1.6x0.8x0.45-PX1.6+5" S2P_R-1.6x0.8x0.45-PX1.6+5 68.25,122 r180 top
R266 "S2P_R-1.6x0.8x0.45-PX1.6+26" S2P_R-1.6x0.8x0.45-PX1.6+26 96,88.5 r180 bottom
R267 "S2P_R-1.6x0.8x0.45-PX1.6+46" S2P_R-1.6x0.8x0.45-PX1.6+46 96,86.5 r180 bottom
R268 "S2P_R-1.6x0.8x0.45-PX1.6+27" S2P_R-1.6x0.8x0.45-PX1.6+27 101,88.5 r180 bottom
R269 "S2P_R-1.6x0.8x0.45-PX1.6+47" S2P_R-1.6x0.8x0.45-PX1.6+47 101,86.5 r0 bottom
R270 "S2P_R-1.6x0.8x0.45-PX1.6+10" S2P_R-1.6x0.8x0.45-PX1.6+10 68.5,117.5 r0 top
R271 "S2P_R-1.6x0.8x0.45-PX1.6+28" S2P_R-1.6x0.8x0.45-PX1.6+28 91.5,100 r0 bottom
R272 "S2P_R-1.6x0.8x0.45-PX1.6+48" S2P_R-1.6x0.8x0.45-PX1.6+48 106,86.5 r0 bottom
R273 "S2P_R-1.6x0.8x0.45-PX1.6+29" S2P_R-1.6x0.8x0.45-PX1.6+29 106,88.5 r180 bottom
R281 "_SG73P1JTTD473J_+4" _SG73P1JTTD473J_+4 268.75,114.5 r270 bottom
R282 "_SG73P2ATTD912J_+3" _SG73P2ATTD912J_+3 271,114.75 r270 bottom
R284 "_RK73B1JTTD222J_+4" _RK73B1JTTD222J_+4 279.5,87 r270 bottom
R285 "_RK73B1JTTD222J_+5" _RK73B1JTTD222J_+5 273,87 r90 bottom
R286 "S2P_R-1.6x0.8x0.45-PX1.6+30" S2P_R-1.6x0.8x0.45-PX1.6+30 281.5,87 r270 bottom
R287 "S2P_R-1.6x0.8x0.45-PX1.6+31" S2P_R-1.6x0.8x0.45-PX1.6+31 271,87 r270 bottom
R288 "_RK73B1JTTD473J_+4" _RK73B1JTTD473J_+4 267.5,101.25 r90 bottom
R289 "_RK73B1JTTD473J_+5" _RK73B1JTTD473J_+5 273.75,101.25 r90 bottom
R290 "S2P_R-1.6x0.8x0.45-PX1.6+54" S2P_R-1.6x0.8x0.45-PX1.6+54 271.75,101.25 r90 bottom
R291 "S2P_R-1.6x0.8x0.45-PX1.6+32" S2P_R-1.6x0.8x0.45-PX1.6+32 269.75,101.25 r270 bottom
R292 "_SG73P1JTTD473J_+5" _SG73P1JTTD473J_+5 268.75,118.75 r270 bottom
R293 "_RK73B1JTTD334J_+2" _RK73B1JTTD334J_+2 281,113.5 r180 bottom
R301 "S2P_R-2x1.25x0.5-PX2+3" S2P_R-2x1.25x0.5-PX2+3 55.75,59.75 r180 top
R302 "_RK73G1JTTD1003D_+3" _RK73G1JTTD1003D_+3 64.75,54.5 r180 top
R303 "S2P_R-1.6x0.8x0.45-PX1.6+59" S2P_R-1.6x0.8x0.45-PX1.6+59 68.5,52.5 r180 top
R304 "_RK73G1JTTD1801D_+3" _RK73G1JTTD1801D_+3 68.5,50.5 r0 top
R307 "_RK73H1JTTD1004F_+3" _RK73H1JTTD1004F_+3 53.25,69.75 r0 top
R308 "S2P_R-10x5.2x1.3-PX10+6" S2P_R-10x5.2x1.3-PX10+6 61,74.5 r180 bottom
R309 "S2P_R-2x1.25x0.5-PX2+7" S2P_R-2x1.25x0.5-PX2+7 201,68.5 r90 top
R310 "_SG73P2ATTD1R0J_+13" _SG73P2ATTD1R0J_+13 173.75,66.5 r270 top
R311 "_SG73P2ATTD100J_+13" _SG73P2ATTD100J_+13 176.75,66.5 r270 top
R312 "_RK73B1JTTD103J_+18" _RK73B1JTTD103J_+18 179,66.25 r90 top
R313 "_SG73P2ATTD1R0J_+14" _SG73P2ATTD1R0J_+14 181.5,66.5 r270 top
R314 "_SG73P2ATTD100J_+14" _SG73P2ATTD100J_+14 184.5,66.5 r270 top
R315 "_RK73B1JTTD103J_+19" _RK73B1JTTD103J_+19 186.75,66.25 r90 top
R316 "_SG73P2ATTD1R0J_+15" _SG73P2ATTD1R0J_+15 189.25,66.5 r270 top
R317 "_SG73P2ATTD100J_+15" _SG73P2ATTD100J_+15 192.25,66.5 r270 top
R318 "_RK73B1JTTD103J_+20" _RK73B1JTTD103J_+20 194.5,66.75 r90 top
R320 "_SG73P2ATTD1R0J_+16" _SG73P2ATTD1R0J_+16 173,47 r90 top
R321 "_SG73P2ATTD100J_+16" _SG73P2ATTD100J_+16 176,47 r90 top
R322 "_RK73B1JTTD103J_+21" _RK73B1JTTD103J_+21 174,50.5 r0 top
R323 "_SG73P2ATTD1R0J_+17" _SG73P2ATTD1R0J_+17 180,47 r90 top
R324 "_SG73P2ATTD100J_+17" _SG73P2ATTD100J_+17 183,47 r90 top
R325 "_RK73B1JTTD103J_+22" _RK73B1JTTD103J_+22 181.5,50.5 r0 top
R326 "_SG73P2ATTD1R0J_+18" _SG73P2ATTD1R0J_+18 187,47 r90 top
R327 "_SG73P2ATTD100J_+18" _SG73P2ATTD100J_+18 190,47 r90 top
R328 "_RK73B1JTTD103J_+23" _RK73B1JTTD103J_+23 188,50.5 r0 top
R329 "S2P_R-10x5.2x1.3-PX10+7" S2P_R-10x5.2x1.3-PX10+7 166.25,76 r180 bottom
R338 "S2P_R-10x5.2x1.3-PX10+8" S2P_R-10x5.2x1.3-PX10+8 224,40 r180 bottom
R347 "_RK73G1JTTD10R0D_+5" _RK73G1JTTD10R0D_+5 123.75,37.25 r180 top
R348 "_RK73G1JTTD2002D_+11" _RK73G1JTTD2002D_+11 115.75,41.25 r270 bottom
R349 "_RK73G1JTTD2002D_+12" _RK73G1JTTD2002D_+12 113.75,41.25 r90 bottom
R350 "_RK73G1JTTD1001D_+11" _RK73G1JTTD1001D_+11 124.25,41.25 r270 bottom
R351 "_RK73G1JTTD2002D_+13" _RK73G1JTTD2002D_+13 120.25,41.25 r90 bottom
R352 "_RK73G1JTTD2002D_+3" _RK73G1JTTD2002D_+3 120.25,37.5 r90 bottom
R353 "_RK73G1JTTD1001D_+12" _RK73G1JTTD1001D_+12 124.25,37.5 r270 bottom
R355 "_RK73G1JTTD10R0D_+6" _RK73G1JTTD10R0D_+6 134.25,37.25 r0 top
R356 "_RK73G1JTTD1102D_+6" _RK73G1JTTD1102D_+6 105.75,41.25 r270 bottom
R357 "_RK73G1JTTD1001D_+13" _RK73G1JTTD1001D_+13 109.75,41.25 r270 bottom
R358 "_RK73G1JTTD1102D_+7" _RK73G1JTTD1102D_+7 111.75,41.25 r90 bottom
R359 "_RK73G1JTTD1001D_+14" _RK73G1JTTD1001D_+14 115.75,37.5 r90 bottom
R360 "_SG73P2ATTD2R2J_+3" _SG73P2ATTD2R2J_+3 276.5,46.25 r270 bottom
R363 "_RK73H1JTTD3303F_+3" _RK73H1JTTD3303F_+3 277.75,58.75 r270 bottom
R364 "S2P_R-1.6x0.8x0.45-PX1.6+6" S2P_R-1.6x0.8x0.45-PX1.6+6 63.5,62 r180 top
R365 "S2P_R-1.6x0.8x0.45-PX1.6+7" S2P_R-1.6x0.8x0.45-PX1.6+7 68.25,62 r180 top
R366 "S2P_R-1.6x0.8x0.45-PX1.6+33" S2P_R-1.6x0.8x0.45-PX1.6+33 96,28.5 r180 bottom
R367 "S2P_R-1.6x0.8x0.45-PX1.6+49" S2P_R-1.6x0.8x0.45-PX1.6+49 96,26.5 r180 bottom
R368 "S2P_R-1.6x0.8x0.45-PX1.6+34" S2P_R-1.6x0.8x0.45-PX1.6+34 101,28.5 r180 bottom
R369 "S2P_R-1.6x0.8x0.45-PX1.6+50" S2P_R-1.6x0.8x0.45-PX1.6+50 101,26.5 r0 bottom
R370 "S2P_R-1.6x0.8x0.45-PX1.6+11" S2P_R-1.6x0.8x0.45-PX1.6+11 68.5,57.5 r0 top
R371 "S2P_R-1.6x0.8x0.45-PX1.6+35" S2P_R-1.6x0.8x0.45-PX1.6+35 91.5,40 r0 bottom
R372 "S2P_R-1.6x0.8x0.45-PX1.6+51" S2P_R-1.6x0.8x0.45-PX1.6+51 106,26.5 r0 bottom
R373 "S2P_R-1.6x0.8x0.45-PX1.6+36" S2P_R-1.6x0.8x0.45-PX1.6+36 106,28.5 r180 bottom
R381 "_SG73P1JTTD473J_+7" _SG73P1JTTD473J_+7 268.75,54.5 r270 bottom
R382 "_SG73P2ATTD912J_" _SG73P2ATTD912J_ 271,54.75 r270 bottom
R384 "_RK73B1JTTD222J_+6" _RK73B1JTTD222J_+6 279.5,27 r270 bottom
R385 "_RK73B1JTTD222J_+7" _RK73B1JTTD222J_+7 273,27 r90 bottom
R386 "S2P_R-1.6x0.8x0.45-PX1.6+37" S2P_R-1.6x0.8x0.45-PX1.6+37 281.5,27 r270 bottom
R387 "S2P_R-1.6x0.8x0.45-PX1.6+38" S2P_R-1.6x0.8x0.45-PX1.6+38 271,27 r270 bottom
R388 "_RK73B1JTTD473J_+6" _RK73B1JTTD473J_+6 267.5,41.25 r90 bottom
R389 "_RK73B1JTTD473J_+7" _RK73B1JTTD473J_+7 273.75,41.25 r90 bottom
R390 "S2P_R-1.6x0.8x0.45-PX1.6+55" S2P_R-1.6x0.8x0.45-PX1.6+55 271.75,41.25 r90 bottom
R391 "S2P_R-1.6x0.8x0.45-PX1.6+39" S2P_R-1.6x0.8x0.45-PX1.6+39 269.75,41.25 r270 bottom
R392 "_SG73P1JTTD473J_+6" _SG73P1JTTD473J_+6 268.75,58.75 r270 bottom
R393 "_RK73B1JTTD334J_+3" _RK73B1JTTD334J_+3 281,53.5 r180 bottom
R401 "_RK73Z1JTTD_+7" _RK73Z1JTTD_+7 168.5,258.5 r180 top
R402 "_RK73Z1JTTD_" _RK73Z1JTTD_ 223,219.5 r0 top
R403 "_RK73H1JTTD6802F_" _RK73H1JTTD6802F_ 211.5,217.5 r270 top
R411 "_RK73Z1JTTD_+1" _RK73Z1JTTD_+1 168.5,198.5 r180 top
R412 "_RK73Z1JTTD_+2" _RK73Z1JTTD_+2 223,159.5 r0 top
R413 "_RK73H1JTTD6802F_+3" _RK73H1JTTD6802F_+3 211.5,157.5 r270 top
R421 "_RK73Z1JTTD_+3" _RK73Z1JTTD_+3 168.5,138.5 r180 top
R422 "_RK73Z1JTTD_+4" _RK73Z1JTTD_+4 223,99.5 r0 top
R423 "_RK73H1JTTD6802F_+2" _RK73H1JTTD6802F_+2 211.5,97.5 r270 top
R431 "_RK73Z1JTTD_+5" _RK73Z1JTTD_+5 168.5,78.5 r180 top
R432 "_RK73Z1JTTD_+6" _RK73Z1JTTD_+6 223,39.5 r0 top
R433 "_RK73H1JTTD6802F_+1" _RK73H1JTTD6802F_+1 211.5,37.5 r270 top
R434 "S2P_R-2x1.25x0.5-PX2" S2P_R-2x1.25x0.5-PX2 54.925,244.95 r180 top
R435 "S2P_R-2x1.25x0.5-PX2" S2P_R-2x1.25x0.5-PX2 54.925,184.942 r180 top
R436 "S2P_R-2x1.25x0.5-PX2" S2P_R-2x1.25x0.5-PX2 54.925,124.935 r180 top
R437 "S2P_R-2x1.25x0.5-PX2" S2P_R-2x1.25x0.5-PX2 54.925,64.927 r180 top
R5111 "_TD11-3H103FT_+2" _TD11-3H103FT_+2 192,257.25 r180 bottom
R5211 "_TD11-3H103FT_" _TD11-3H103FT_ 192,197.25 r180 bottom
R5311 "_TD11-3H103FT_+1" _TD11-3H103FT_+1 192,137.25 r180 bottom
R5411 "_TD11-3H103FT_+3" _TD11-3H103FT_+3 192,77.25 r180 bottom
TN11 "D2P_TN-L-H2x10-2" D2P_TN-L-H2x10-2 38,250 r0 top
TN12 "D2P_TN-L-H2x10-2" D2P_TN-L-H2x10-2 64,224 r0 top
TN13 "D2P_TN-R-H2x10-2" D2P_TN-R-H2x10-2 332,250 r0 top
TN14 "D2P_TN-R-H2x10-2" D2P_TN-R-H2x10-2 319,216 r0 top
TN21 "D2P_TN-L-H2x10-2" D2P_TN-L-H2x10-2 38,190 r0 top
TN22 "D2P_TN-L-H2x10-2" D2P_TN-L-H2x10-2 64,164 r0 top
TN23 "D2P_TN-R-H2x10-2" D2P_TN-R-H2x10-2 332,190 r0 top
TN24 "D2P_TN-R-H2x10-2" D2P_TN-R-H2x10-2 319,156 r0 top
TN31 "D2P_TN-L-H2x10-2" D2P_TN-L-H2x10-2 38,130 r0 top
TN32 "D2P_TN-L-H2x10-2" D2P_TN-L-H2x10-2 64,104 r0 top
TN33 "D2P_TN-R-H2x10-2" D2P_TN-R-H2x10-2 332,130 r0 top
TN34 "D2P_TN-R-H2x10-2" D2P_TN-R-H2x10-2 319,96 r0 top
TN41 "D2P_TN-L-H2x10-2" D2P_TN-L-H2x10-2 38,70 r0 top
TN42 "D2P_TN-L-H2x10-2" D2P_TN-L-H2x10-2 64,44 r0 top
TN43 "D2P_TN-R-H2x10-2" D2P_TN-R-H2x10-2 332,70 r0 top
TN44 "D2P_TN-R-H2x10-2" D2P_TN-R-H2x10-2 319,36 r0 top
TP4 "_Direct_In_PAD-D2_" _Direct_In_PAD-D2_ 175.5,254.5 r0 top
TP6 "_Direct_In_PAD-D2_+1" _Direct_In_PAD-D2_+1 191.5,254.5 r0 top
TP7 "_Direct_In_PAD-D2_+2" _Direct_In_PAD-D2_+2 175.5,238.5 r0 top
TP9 "_Direct_In_PAD-D2_+3" _Direct_In_PAD-D2_+3 191.5,238.5 r0 top
TP14 "_Direct_In_PAD-D2_+4" _Direct_In_PAD-D2_+4 176.5,242.875 r0 top
TP16 "_Direct_In_PAD-D2_+5" _Direct_In_PAD-D2_+5 193.375,242.875 r0 top
TP17 "_Direct_In_PAD-D2_+46" _Direct_In_PAD-D2_+46 177.125,233.25 r0 top
TP19 "_Direct_In_PAD-D2_+6" _Direct_In_PAD-D2_+6 193.125,233.25 r0 top
TP24 "_Direct_In_PAD-D2_+7" _Direct_In_PAD-D2_+7 173.595,242.875 r0 top
TP26 "_Direct_In_PAD-D2_+8" _Direct_In_PAD-D2_+8 190.5,242.875 r0 top
TP27 "_Direct_In_PAD-D2_+9" _Direct_In_PAD-D2_+9 173.595,233.25 r0 top
TP29 "_Direct_In_PAD-D2_+10" _Direct_In_PAD-D2_+10 189.595,233.25 r0 top
TP104 "_Direct_In_PAD-D2_+11" _Direct_In_PAD-D2_+11 175.5,194.5 r0 top
TP106 "_Direct_In_PAD-D2_+12" _Direct_In_PAD-D2_+12 191.5,194.5 r0 top
TP107 "_Direct_In_PAD-D2_+13" _Direct_In_PAD-D2_+13 175.5,178.5 r0 top
TP109 "_Direct_In_PAD-D2_+14" _Direct_In_PAD-D2_+14 191.5,178.5 r0 top
TP114 "_Direct_In_PAD-D2_+15" _Direct_In_PAD-D2_+15 176.5,182.875 r0 top
TP116 "_Direct_In_PAD-D2_+16" _Direct_In_PAD-D2_+16 193.375,182.875 r0 top
TP117 "S1P_CP-D2" S1P_CP-D2 177.125,173.25 r0 top
TP119 "_Direct_In_PAD-D2_+17" _Direct_In_PAD-D2_+17 193.125,173.25 r0 top
TP124 "_Direct_In_PAD-D2_+18" _Direct_In_PAD-D2_+18 173.595,182.875 r0 top
TP126 "_Direct_In_PAD-D2_+19" _Direct_In_PAD-D2_+19 190.5,182.875 r0 top
TP127 "_Direct_In_PAD-D2_+20" _Direct_In_PAD-D2_+20 173.595,173.25 r0 top
TP129 "_Direct_In_PAD-D2_+21" _Direct_In_PAD-D2_+21 189.595,173.25 r0 top
TP204 "_Direct_In_PAD-D2_+22" _Direct_In_PAD-D2_+22 175.5,134.5 r0 top
TP206 "_Direct_In_PAD-D2_+23" _Direct_In_PAD-D2_+23 191.5,134.5 r0 top
TP207 "_Direct_In_PAD-D2_+24" _Direct_In_PAD-D2_+24 175.5,118.5 r0 top
TP209 "_Direct_In_PAD-D2_+25" _Direct_In_PAD-D2_+25 191.5,118.5 r0 top
TP214 "_Direct_In_PAD-D2_+26" _Direct_In_PAD-D2_+26 176.5,122.875 r0 top
TP216 "_Direct_In_PAD-D2_+27" _Direct_In_PAD-D2_+27 193.375,122.875 r0 top
TP217 "_Direct_In_PAD-D2_+28" _Direct_In_PAD-D2_+28 177.125,113.25 r0 top
TP219 "_Direct_In_PAD-D2_+29" _Direct_In_PAD-D2_+29 193.125,113.25 r0 top
TP224 "_Direct_In_PAD-D2_+30" _Direct_In_PAD-D2_+30 173.595,122.875 r0 top
TP226 "_Direct_In_PAD-D2_+31" _Direct_In_PAD-D2_+31 190.5,122.875 r0 top
TP227 "_Direct_In_PAD-D2_+32" _Direct_In_PAD-D2_+32 173.595,113.25 r0 top
TP229 "_Direct_In_PAD-D2_+33" _Direct_In_PAD-D2_+33 189.595,113.25 r0 top
TP304 "_Direct_In_PAD-D2_+34" _Direct_In_PAD-D2_+34 175.5,74.5 r0 top
TP306 "_Direct_In_PAD-D2_+35" _Direct_In_PAD-D2_+35 191.5,74.5 r0 top
TP307 "_Direct_In_PAD-D2_+36" _Direct_In_PAD-D2_+36 175.5,58.5 r0 top
TP309 "_Direct_In_PAD-D2_+37" _Direct_In_PAD-D2_+37 191.5,58.5 r0 top
TP314 "_Direct_In_PAD-D2_+38" _Direct_In_PAD-D2_+38 176.5,62.875 r0 top
TP316 "_Direct_In_PAD-D2_+39" _Direct_In_PAD-D2_+39 193.375,62.875 r0 top
TP317 "_Direct_In_PAD-D2_+40" _Direct_In_PAD-D2_+40 177.125,53.25 r0 top
TP319 "_Direct_In_PAD-D2_+41" _Direct_In_PAD-D2_+41 193.125,53.25 r0 top
TP324 "_Direct_In_PAD-D2_+42" _Direct_In_PAD-D2_+42 173.595,62.875 r0 top
TP326 "_Direct_In_PAD-D2_+43" _Direct_In_PAD-D2_+43 190.5,62.875 r0 top
TP327 "_Direct_In_PAD-D2_+44" _Direct_In_PAD-D2_+44 173.595,53.25 r0 top
TP329 "_Direct_In_PAD-D2_+45" _Direct_In_PAD-D2_+45 189.595,53.25 r0 top

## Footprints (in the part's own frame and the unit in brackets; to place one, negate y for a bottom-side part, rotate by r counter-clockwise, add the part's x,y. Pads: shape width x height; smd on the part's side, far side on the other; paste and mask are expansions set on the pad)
1SS403E [mm] "KC00080BKP"
  rect 0.6x0.8 smd paste-0.9 mask+0: 1(-0.85,0) 2(0.85,0)
_1SS403_ [mm] "KC00080BKP"
  rect 0.9x0.5 smd paste-0.9 mask+0: 1(0.85,0) 2(-0.85,0)
_1SS403_+1 [mm] "KC00080BKP"
  rect 0.9x0.5 smd paste-0.9 mask+0: 1(0.85,0) 2(-0.85,0)
_1SS403_+2 [mm] "KC00080BKP"
  rect 0.9x0.5 smd paste-0.9 mask+0: 1(0.85,0) 2(-0.85,0)
_1SS403_+3 [mm] "KC00080BKP"
  rect 0.9x0.5 smd paste-0.9 mask+0: 1(0.85,0) 2(-0.85,0)
_1SS403_+4 [mm] "KC00080BKP"
  rect 0.9x0.5 smd paste-0.9 mask+0: 1(0.85,0) 2(-0.85,0)
_1SS403_+5 [mm] "KC00080BKP"
  rect 0.9x0.5 smd paste-0.9 mask+0: 1(0.85,0) 2(-0.85,0)
_1SS403_+6 [mm] "KC00080BKP"
  rect 0.9x0.5 smd paste-0.9 mask+0: 1(0.85,0) 2(-0.85,0)
_1SS403_+7 [mm] "KC00080BKP"
  rect 0.9x0.5 smd paste-0.9 mask+0: 1(0.85,0) 2(-0.85,0)
_1SS403_+8 [mm] "KC00080BKP"
  rect 0.9x0.5 smd paste-0.9 mask+0: 1(0.85,0) 2(-0.85,0)
_1SS403_+9 [mm] "KC00080BKP"
  rect 0.9x0.5 smd paste-0.9 mask+0: 1(0.85,0) 2(-0.85,0)
_1SS403_+10 [mm] "KC00080BKP"
  rect 0.9x0.5 smd paste-0.9 mask+0: 1(0.85,0) 2(-0.85,0)
_1SS403_+11 [mm] "KC00080BKP"
  rect 0.9x0.5 smd paste-0.9 mask+0: 1(0.85,0) 2(-0.85,0)
_1SS403_+12 [mm] "KC00080BKP"
  rect 0.9x0.5 smd paste-0.9 mask+0: 1(0.85,0) 2(-0.85,0)
_1SS403_+13 [mm] "KC00080BKP"
  rect 0.9x0.5 smd paste-0.9 mask+0: 1(0.85,0) 2(-0.85,0)
_1SS403_+14 [mm] "KC00080BKP"
  rect 0.9x0.5 smd paste-0.9 mask+0: 1(0.85,0) 2(-0.85,0)
_1SS403_+15 [mm] "KC00080BKP"
  rect 0.9x0.5 smd paste-0.9 mask+0: 1(0.85,0) 2(-0.85,0)
_1SS403_+16 [mm] "KC00080BKP"
  rect 0.9x0.5 smd paste-0.9 mask+0: 1(0.85,0) 2(-0.85,0)
_1SS403_+17 [mm] "KC00080BKP"
  rect 0.9x0.5 smd paste-0.9 mask+0: 1(0.85,0) 2(-0.85,0)
_1SS403_+18 [mm] "KC00080BKP"
  rect 0.9x0.5 smd paste-0.9 mask+0: 1(0.85,0) 2(-0.85,0)
_1SS403_+19 [mm] "KC00080BKP"
  rect 0.9x0.5 smd paste-0.9 mask+0: 1(0.85,0) 2(-0.85,0)
_1SS403_+20 [mm] "KC00080BKP"
  rect 0.9x0.5 smd paste-0.9 mask+0: 1(0.85,0) 2(-0.85,0)
_1SS403_+21 [mm] "KC00080BKP"
  rect 0.9x0.5 smd paste-0.9 mask+0: 1(0.85,0) 2(-0.85,0)
_1SS403_+22 [mm] "KC00080BKP"
  rect 0.9x0.5 smd paste-0.9 mask+0: 1(0.85,0) 2(-0.85,0)
_1SS403_+23 [mm] "KC00080BKP"
  rect 0.9x0.5 smd paste-0.9 mask+0: 1(0.85,0) 2(-0.85,0)
_B2B-EH_ [mm] "KC00080BKP"
  round 1.9 hole 1.1 paste-2 mask+0: 1(-1.25,0) 2(1.25,0)
_B2P-VH_ [mm] "KC00080BKP"
  round 2.6 hole 1.8 paste-2.7 mask+0: 1(-1.98,0) 2(1.98,0)
_CGA5F2C0G1H333J085AD_ [mm] "KC00080BKP"
  rect 1.15x1.8 smd paste-1.8 mask+0: 1(-1.525,0) 2(1.525,0)
_CGA5F2C0G1H333J085AD_+1 [mm] "KC00080BKP"
  rect 1.15x1.8 smd paste-1.8 mask+0: 1(-1.525,0) 2(1.525,0)
_CGA5F2C0G1H333J085AD_+2 [mm] "KC00080BKP"
  rect 1.15x1.8 smd paste-1.8 mask+0: 1(-1.525,0) 2(1.525,0)
_CGA5F2C0G1H333J085AD_+3 [mm] "KC00080BKP"
  rect 1.15x1.8 smd paste-1.8 mask+0: 1(-1.525,0) 2(1.525,0)
_CGA5F2C0G1H333J085AD_+4 [mm] "KC00080BKP"
  rect 1.15x1.8 smd paste-1.8 mask+0: 1(-1.525,0) 2(1.525,0)
_CGA5F2C0G1H333J085AD_+5 [mm] "KC00080BKP"
  rect 1.15x1.8 smd paste-1.8 mask+0: 1(-1.525,0) 2(1.525,0)
_CGA5F2C0G1H333J085AD_+6 [mm] "KC00080BKP"
  rect 1.15x1.8 smd paste-1.8 mask+0: 1(-1.525,0) 2(1.525,0)
_CGA5F2C0G1H333J085AD_+7 [mm] "KC00080BKP"
  rect 1.15x1.8 smd paste-1.8 mask+0: 1(-1.525,0) 2(1.525,0)
_CGA5L2C0G1H104J160AA_ [mm] "KC00080BKP"
  rect 1.15x1.8 smd paste-1.8 mask+0: 1(-1.525,0) 2(1.525,0)
_CGA5L2C0G1H104J160AA_+1 [mm] "KC00080BKP"
  rect 1.15x1.8 smd paste-1.8 mask+0: 1(-1.525,0) 2(1.525,0)
_CGA5L2C0G1H104J160AA_+2 [mm] "KC00080BKP"
  rect 1.15x1.8 smd paste-1.8 mask+0: 1(-1.525,0) 2(1.525,0)
_CGA5L2C0G1H104J160AA_+3 [mm] "KC00080BKP"
  rect 1.15x1.8 smd paste-1.8 mask+0: 1(-1.525,0) 2(1.525,0)
_CGA5L2X7R2A104K160AA_ [mm] "KC00080BKP"
  rect 1.15x1.8 smd paste-1.8 mask+0: 1(-1.525,0) 2(1.525,0)
_CGA5L2X7R2A104K160AA_+1 [mm] "KC00080BKP"
  rect 1.15x1.8 smd paste-1.8 mask+0: 1(-1.525,0) 2(1.525,0)
_CGA5L2X7R2A104K160AA_+2 [mm] "KC00080BKP"
  rect 1.15x1.8 smd paste-1.8 mask+0: 1(-1.525,0) 2(1.525,0)
_CGA5L2X7R2A104K160AA_+3 [mm] "KC00080BKP"
  rect 1.15x1.8 smd paste-1.8 mask+0: 1(-1.525,0) 2(1.525,0)
_CGA5L2X7R2A474K160AA_ [mm] "KC00080BKP"
  rect 1.15x1.8 smd paste-1.8 mask+0: 1(-1.525,0) 2(1.525,0)
_CGA5L2X7R2A474K160AA_+1 [mm] "KC00080BKP"
  rect 1.15x1.8 smd paste-1.8 mask+0: 1(-1.525,0) 2(1.525,0)
_CGA5L2X7R2A474K160AA_+2 [mm] "KC00080BKP"
  rect 1.15x1.8 smd paste-1.8 mask+0: 1(-1.525,0) 2(1.525,0)
_CGA5L2X7R2A474K160AA_+3 [mm] "KC00080BKP"
  rect 1.15x1.8 smd paste-1.8 mask+0: 1(-1.525,0) 2(1.525,0)
_CGA5L2X7R2A474K160AA_+4 [mm] "KC00080BKP"
  rect 1.15x1.8 smd paste-1.8 mask+0: 1(-1.525,0) 2(1.525,0)
_CGA5L2X7R2A474K160AA_+5 [mm] "KC00080BKP"
  rect 1.15x1.8 smd paste-1.8 mask+0: 1(-1.525,0) 2(1.525,0)
_CGA5L2X7R2A474K160AA_+6 [mm] "KC00080BKP"
  rect 1.15x1.8 smd paste-1.8 mask+0: 1(-1.525,0) 2(1.525,0)
_CGA5L2X7R2A474K160AA_+7 [mm] "KC00080BKP"
  rect 1.15x1.8 smd paste-1.8 mask+0: 1(-1.525,0) 2(1.525,0)
_CGA6M3X7R1H225K200AB_ [mm] "KC00080BKP"
  rect 1.15x2.7 smd paste-2.7 mask+0: 1(-1.525,0) 2(1.525,0)
_CGA6M3X7R1H225K200AB_+1 [mm] "KC00080BKP"
  rect 1.15x2.7 smd paste-2.7 mask+0: 1(-1.525,0) 2(1.525,0)
_CGA6M3X7R1H225K200AB_+2 [mm] "KC00080BKP"
  rect 1.15x2.7 smd paste-2.7 mask+0: 1(-1.525,0) 2(1.525,0)
_CGA6M3X7R1H225K200AB_+3 [mm] "KC00080BKP"
  rect 1.15x2.7 smd paste-2.7 mask+0: 1(-1.525,0) 2(1.525,0)
_CGA6M3X7R1H225K200AB_+4 [mm] "KC00080BKP"
  rect 1.15x2.7 smd paste-2.7 mask+0: 1(-1.525,0) 2(1.525,0)
_CGA6M3X7R1H225K200AB_+5 [mm] "KC00080BKP"
  rect 1.15x2.7 smd paste-2.7 mask+0: 1(-1.525,0) 2(1.525,0)
_CGA6M3X7R1H225K200AB_+6 [mm] "KC00080BKP"
  rect 1.15x2.7 smd paste-2.7 mask+0: 1(-1.525,0) 2(1.525,0)
_CGA6M3X7R1H225K200AB_+7 [mm] "KC00080BKP"
  rect 1.15x2.7 smd paste-2.7 mask+0: 1(-1.525,0) 2(1.525,0)
_CGA6M3X7R1H225K200AB_+8 [mm] "KC00080BKP"
  rect 1.15x2.7 smd paste-2.7 mask+0: 1(1.525,0) 2(-1.525,0)
_CGA6M3X7R1H225K200AB_+9 [mm] "KC00080BKP"
  rect 1.15x2.7 smd paste-2.7 mask+0: 1(-1.525,0) 2(1.525,0)
_CGA6M3X7R1H225K200AB_+10 [mm] "KC00080BKP"
  rect 1.15x2.7 smd paste-2.7 mask+0: 1(1.525,0) 2(-1.525,0)
_CGA6M3X7R1H225K200AB_+11 [mm] "KC00080BKP"
  rect 1.15x2.7 smd paste-2.7 mask+0: 1(-1.525,0) 2(1.525,0)
_CGA6M3X7R1H225K200AB_+12 [mm] "KC00080BKP"
  rect 1.15x2.7 smd paste-2.7 mask+0: 1(1.525,0) 2(-1.525,0)
_CGA6M3X7R1H225K200AB_+13 [mm] "KC00080BKP"
  rect 1.15x2.7 smd paste-2.7 mask+0: 1(-1.525,0) 2(1.525,0)
_CGA6M3X7R1H225K200AB_+14 [mm] "KC00080BKP"
  rect 1.15x2.7 smd paste-2.7 mask+0: 1(-1.525,0) 2(1.525,0)
_CGA6M3X7R1H225K200AB_+15 [mm] "KC00080BKP"
  rect 1.15x2.7 smd paste-2.7 mask+0: 1(-1.525,0) 2(1.525,0)
_CGA6M3X7R1H225K200AB_+16 [mm] "KC00080BKP"
  rect 1.15x2.7 smd paste-2.7 mask+0: 1(-1.525,0) 2(1.525,0)
_CGA6M3X7R1H225K200AB_+17 [mm] "KC00080BKP"
  rect 1.15x2.7 smd paste-2.7 mask+0: 1(-1.525,0) 2(1.525,0)
_CGA6M3X7R1H225K200AB_+18 [mm] "KC00080BKP"
  rect 1.15x2.7 smd paste-2.7 mask+0: 1(-1.525,0) 2(1.525,0)
_CGA6M3X7R1H225K200AB_+19 [mm] "KC00080BKP"
  rect 1.15x2.7 smd paste-2.7 mask+0: 1(-1.525,0) 2(1.525,0)
_CGA6M3X7R1H225K200AB_+20 [mm] "KC00080BKP"
  rect 1.15x2.7 smd paste-2.7 mask+0: 1(-1.525,0) 2(1.525,0)
_CGA6M3X7R1H225K200AB_+21 [mm] "KC00080BKP"
  rect 1.15x2.7 smd paste-2.7 mask+0: 1(-1.525,0) 2(1.525,0)
_CGA6M3X7R1H225K200AB_+22 [mm] "KC00080BKP"
  rect 1.15x2.7 smd paste-2.7 mask+0: 1(-1.525,0) 2(1.525,0)
_CGA6M3X7R1H225K200AB_+23 [mm] "KC00080BKP"
  rect 1.15x2.7 smd paste-2.7 mask+0: 1(1.525,0) 2(-1.525,0)
_Direct_In_PAD-D2_ [mm] "KC00080BKP"
  round 2 smd paste-2 mask+0: 1(0,0)
_Direct_In_PAD-D2_+1 [mm] "KC00080BKP"
  round 2 smd paste-2 mask+0: 1(0,0)
_Direct_In_PAD-D2_+2 [mm] "KC00080BKP"
  round 2 smd paste-2 mask+0: 1(0,0)
_Direct_In_PAD-D2_+3 [mm] "KC00080BKP"
  round 2 smd paste-2 mask+0: 1(0,0)
_Direct_In_PAD-D2_+4 [mm] "KC00080BKP"
  round 2 smd paste-2 mask+0: 1(0,0)
_Direct_In_PAD-D2_+5 [mm] "KC00080BKP"
  round 2 smd paste-2 mask+0: 1(0,0)
_Direct_In_PAD-D2_+6 [mm] "KC00080BKP"
  round 2 smd paste-2 mask+0: 1(0,0)
_Direct_In_PAD-D2_+7 [mm] "KC00080BKP"
  round 2 smd paste-2 mask+0: 1(0,0)
_Direct_In_PAD-D2_+8 [mm] "KC00080BKP"
  round 2 smd paste-2 mask+0: 1(0,0)
_Direct_In_PAD-D2_+9 [mm] "KC00080BKP"
  round 2 smd paste-2 mask+0: 1(0,0)
_Direct_In_PAD-D2_+10 [mm] "KC00080BKP"
  round 2 smd paste-2 mask+0: 1(0,0)
_Direct_In_PAD-D2_+11 [mm] "KC00080BKP"
  round 2 smd paste-2 mask+0: 1(0,0)
_Direct_In_PAD-D2_+12 [mm] "KC00080BKP"
  round 2 smd paste-2 mask+0: 1(0,0)
_Direct_In_PAD-D2_+13 [mm] "KC00080BKP"
  round 2 smd paste-2 mask+0: 1(0,0)
_Direct_In_PAD-D2_+14 [mm] "KC00080BKP"
  round 2 smd paste-2 mask+0: 1(0,0)
_Direct_In_PAD-D2_+15 [mm] "KC00080BKP"
  round 2 smd paste-2 mask+0: 1(0,0)
_Direct_In_PAD-D2_+16 [mm] "KC00080BKP"
  round 2 smd paste-2 mask+0: 1(0,0)
_Direct_In_PAD-D2_+17 [mm] "KC00080BKP"
  round 2 smd paste-2 mask+0: 1(0,0)
_Direct_In_PAD-D2_+18 [mm] "KC00080BKP"
  round 2 smd paste-2 mask+0: 1(0,0)
_Direct_In_PAD-D2_+19 [mm] "KC00080BKP"
  round 2 smd paste-2 mask+0: 1(0,0)
_Direct_In_PAD-D2_+20 [mm] "KC00080BKP"
  round 2 smd paste-2 mask+0: 1(0,0)
_Direct_In_PAD-D2_+21 [mm] "KC00080BKP"
  round 2 smd paste-2 mask+0: 1(0,0)
_Direct_In_PAD-D2_+22 [mm] "KC00080BKP"
  round 2 smd paste-2 mask+0: 1(0,0)
_Direct_In_PAD-D2_+23 [mm] "KC00080BKP"
  round 2 smd paste-2 mask+0: 1(0,0)
_Direct_In_PAD-D2_+24 [mm] "KC00080BKP"
  round 2 smd paste-2 mask+0: 1(0,0)
_Direct_In_PAD-D2_+25 [mm] "KC00080BKP"
  round 2 smd paste-2 mask+0: 1(0,0)
_Direct_In_PAD-D2_+26 [mm] "KC00080BKP"
  round 2 smd paste-2 mask+0: 1(0,0)
_Direct_In_PAD-D2_+27 [mm] "KC00080BKP"
  round 2 smd paste-2 mask+0: 1(0,0)
_Direct_In_PAD-D2_+28 [mm] "KC00080BKP"
  round 2 smd paste-2 mask+0: 1(0,0)
_Direct_In_PAD-D2_+29 [mm] "KC00080BKP"
  round 2 smd paste-2 mask+0: 1(0,0)
_Direct_In_PAD-D2_+30 [mm] "KC00080BKP"
  round 2 smd paste-2 mask+0: 1(0,0)
_Direct_In_PAD-D2_+31 [mm] "KC00080BKP"
  round 2 smd paste-2 mask+0: 1(0,0)
_Direct_In_PAD-D2_+32 [mm] "KC00080BKP"
  round 2 smd paste-2 mask+0: 1(0,0)
_Direct_In_PAD-D2_+33 [mm] "KC00080BKP"
  round 2 smd paste-2 mask+0: 1(0,0)
_Direct_In_PAD-D2_+34 [mm] "KC00080BKP"
  round 2 smd paste-2 mask+0: 1(0,0)
_Direct_In_PAD-D2_+35 [mm] "KC00080BKP"
  round 2 smd paste-2 mask+0: 1(0,0)
_Direct_In_PAD-D2_+36 [mm] "KC00080BKP"
  round 2 smd paste-2 mask+0: 1(0,0)
_Direct_In_PAD-D2_+37 [mm] "KC00080BKP"
  round 2 smd paste-2 mask+0: 1(0,0)
_Direct_In_PAD-D2_+38 [mm] "KC00080BKP"
  round 2 smd paste-2 mask+0: 1(0,0)
_Direct_In_PAD-D2_+39 [mm] "KC00080BKP"
  round 2 smd paste-2 mask+0: 1(0,0)
_Direct_In_PAD-D2_+40 [mm] "KC00080BKP"
  round 2 smd paste-2 mask+0: 1(0,0)
_Direct_In_PAD-D2_+41 [mm] "KC00080BKP"
  round 2 smd paste-2 mask+0: 1(0,0)
_Direct_In_PAD-D2_+42 [mm] "KC00080BKP"
  round 2 smd paste-2 mask+0: 1(0,0)
_Direct_In_PAD-D2_+43 [mm] "KC00080BKP"
  round 2 smd paste-2 mask+0: 1(0,0)
_Direct_In_PAD-D2_+44 [mm] "KC00080BKP"
  round 2 smd paste-2 mask+0: 1(0,0)
_Direct_In_PAD-D2_+45 [mm] "KC00080BKP"
  round 2 smd paste-2 mask+0: 1(0,0)
_Direct_In_PAD-D2_+46 [mm] "KC00080BKP"
  round 2 smd paste-2 mask+0: 1(0,0)
_HW-1-S_ [mm] "KC00080BKP"
  rect 5.2x2 smd paste-5.2 mask+0: 1(0,0)
_HW-1-S_+1 [mm] "KC00080BKP"
  rect 5.2x2 smd paste-5.2 mask+0: 1(0,0)
_HW-1-S_+2 [mm] "KC00080BKP"
  rect 5.2x2 smd paste-5.2 mask+0: 1(0,0)
_HW-1-S_+3 [mm] "KC00080BKP"
  rect 5.2x2 smd paste-5.2 mask+0: 1(0,0)
_HW-1-S_+4 [mm] "KC00080BKP"
  rect 5.2x2 smd paste-5.2 mask+0: 1(0,0)
_HW-1-S_+5 [mm] "KC00080BKP"
  rect 5.2x2 smd paste-5.2 mask+0: 1(0,0)
_HW-1-S_+6 [mm] "KC00080BKP"
  rect 5.2x2 smd paste-5.2 mask+0: 1(0,0)
_HW-1-S_+7 [mm] "KC00080BKP"
  rect 5.2x2 smd paste-5.2 mask+0: 1(0,0)
_HW-1-S_+8 [mm] "KC00080BKP"
  rect 5.2x2 smd paste-5.2 mask+0: 1(0,0)
_HW-1-S_+9 [mm] "KC00080BKP"
  rect 5.2x2 smd paste-5.2 mask+0: 1(0,0)
_HW-1-S_+10 [mm] "KC00080BKP"
  rect 5.2x2 smd paste-5.2 mask+0: 1(0,0)
_HW-1-S_+11 [mm] "KC00080BKP"
  rect 5.2x2 smd paste-5.2 mask+0: 1(0,0)
_HW-1-S_+12 [mm] "KC00080BKP"
  rect 5.2x2 smd paste-5.2 mask+0: 1(0,0)
_HW-1-S_+13 [mm] "KC00080BKP"
  rect 5.2x2 smd paste-5.2 mask+0: 1(0,0)
_HW-1-S_+14 [mm] "KC00080BKP"
  rect 5.2x2 smd paste-5.2 mask+0: 1(0,0)
_HW-1-S_+15 [mm] "KC00080BKP"
  rect 5.2x2 smd paste-5.2 mask+0: 1(0,0)
_HW-1-S_+16 [mm] "KC00080BKP"
  rect 5.2x2 smd paste-5.2 mask+0: 1(0,0)
_HW-1-S_+17 [mm] "KC00080BKP"
  rect 5.2x2 smd paste-5.2 mask+0: 1(0,0)
_HW-1-S_+18 [mm] "KC00080BKP"
  rect 5.2x2 smd paste-5.2 mask+0: 1(0,0)
_HW-1-S_+19 [mm] "KC00080BKP"
  rect 5.2x2 smd paste-5.2 mask+0: 1(0,0)
_HW-1-S_+20 [mm] "KC00080BKP"
  rect 5.2x2 smd paste-5.2 mask+0: 1(0,0)
_HW-1-S_+21 [mm] "KC00080BKP"
  rect 5.2x2 smd paste-5.2 mask+0: 1(0,0)
_HW-1-S_+22 [mm] "KC00080BKP"
  rect 5.2x2 smd paste-5.2 mask+0: 1(0,0)
_HW-1-S_+23 [mm] "KC00080BKP"
  rect 5.2x2 smd paste-5.2 mask+0: 1(0,0)
_HW-1-S_+24 [mm] "KC00080BKP"
  rect 5.2x2 smd paste-5.2 mask+0: 1(0,0)
_HW-1-S_+25 [mm] "KC00080BKP"
  rect 5.2x2 smd paste-5.2 mask+0: 1(0,0)
_HW-1-S_+26 [mm] "KC00080BKP"
  rect 5.2x2 smd paste-5.2 mask+0: 1(0,0)
_HW-1-S_+27 [mm] "KC00080BKP"
  rect 5.2x2 smd paste-5.2 mask+0: 1(0,0)
_LTC4364HMS-2#PBF_ [mm] "KC00080BKP"
  rect 0.27x1.2 smd paste-1.2 mask+0: 1(-1.75,-2.35) 2(-1.25,-2.35) 3(-0.75,-2.35) 4(-0.25,-2.35) 5(0.25,-2.35) 6(0.75,-2.35) 7(1.25,-2.35) 8(1.75,-2.35) 9(1.75,2.35) 10(1.25,2.35) 11(0.75,2.35) 12(0.25,2.35) 13(-0.25,2.35) 14(-0.75,2.35) 15(-1.25,2.35) 16(-1.75,2.35)
_LTC4364HMS-2#PBF_+1 [mm] "KC00080BKP"
  rect 0.27x1.2 smd paste-1.2 mask+0: 1(-1.75,-2.35) 2(-1.25,-2.35) 3(-0.75,-2.35) 4(-0.25,-2.35) 5(0.25,-2.35) 6(0.75,-2.35) 7(1.25,-2.35) 8(1.75,-2.35) 9(1.75,2.35) 10(1.25,2.35) 11(0.75,2.35) 12(0.25,2.35) 13(-0.25,2.35) 14(-0.75,2.35) 15(-1.25,2.35) 16(-1.75,2.35)
_LTC4364HMS-2#PBF_+2 [mm] "KC00080BKP"
  rect 0.27x1.2 smd paste-1.2 mask+0: 1(-1.75,-2.35) 2(-1.25,-2.35) 3(-0.75,-2.35) 4(-0.25,-2.35) 5(0.25,-2.35) 6(0.75,-2.35) 7(1.25,-2.35) 8(1.75,-2.35) 9(1.75,2.35) 10(1.25,2.35) 11(0.75,2.35) 12(0.25,2.35) 13(-0.25,2.35) 14(-0.75,2.35) 15(-1.25,2.35) 16(-1.75,2.35)
_LTC4364HMS-2#PBF_+3 [mm] "KC00080BKP"
  rect 0.27x1.2 smd paste-1.2 mask+0: 1(-1.75,-2.35) 2(-1.25,-2.35) 3(-0.75,-2.35) 4(-0.25,-2.35) 5(0.25,-2.35) 6(0.75,-2.35) 7(1.25,-2.35) 8(1.75,-2.35) 9(1.75,2.35) 10(1.25,2.35) 11(0.75,2.35) 12(0.25,2.35) 13(-0.25,2.35) 14(-0.75,2.35) 15(-1.25,2.35) 16(-1.75,2.35)
_PCV1J390MCL2GS_ [mil] "KC00080BKP"
  round 7 smd paste-7 mask+0: 1(-137.79,0) 2(137.79,0)
_PCV1J390MCL2GS_+1 [mil] "KC00080BKP"
  round 7 smd paste-7 mask+0: 1(-137.79,0) 2(137.79,0)
_PCV1J390MCL2GS_+2 [mil] "KC00080BKP"
  round 7 smd paste-7 mask+0: 1(-137.8,0) 2(137.79,0)
_PCV1J390MCL2GS_+3 [mil] "KC00080BKP"
  round 7 smd paste-7 mask+0: 1(-137.8,0) 2(137.79,0)
_PCV1J390MCL2GS_+4 [mil] "KC00080BKP"
  round 7 smd paste-7 mask+0: 1(-137.8,0) 2(137.79,0)
_PCV1J390MCL2GS_+5 [mil] "KC00080BKP"
  round 7 smd paste-7 mask+0: 1(-137.8,0) 2(137.79,0)
_PCV1J390MCL2GS_+6 [mil] "KC00080BKP"
  round 7 smd paste-7 mask+0: 1(-137.8,0) 2(137.79,0)
_PCV1J390MCL2GS_+7 [mil] "KC00080BKP"
  round 7 smd paste-7 mask+0: 1(-137.8,0) 2(137.79,0)
_PCV1J390MCL2GS_+8 [mil] "KC00080BKP"
  round 7 smd paste-7 mask+0: 1(-137.79,0) 2(137.8,0)
_PCV1J390MCL2GS_+9 [mil] "KC00080BKP"
  round 7 smd paste-7 mask+0: 1(-137.79,0) 2(137.8,0)
_PCV1J390MCL2GS_+10 [mil] "KC00080BKP"
  round 7 smd paste-7 mask+0: 1(-137.8,0) 2(137.8,0)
